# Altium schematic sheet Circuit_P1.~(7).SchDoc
size 431 x 279 mm; Date: Not shown in title block; ApprovedBy: Not shown in title block; CheckedBy: Not shown in title block; Author: Not shown in title block; CompanyName: Not shown in title block; Engineer: Not shown in title block; Organization: Not shown in title block; Address1: Not shown in title block; Address2: Not shown in title block; Address3: Not shown in title block; Address4: Not shown in title block; DocumentNumber: 1; Revision: Use project parameter SCH_Rev; SheetNumber: 1; SheetTotal: 2; PageSetup: Record=PageOptions¦CenterHorizontal=True¦CenterVertical=True¦PrintScale=1.00¦XCorrection=1.00¦YCorrection=1.00¦PrintKind=0¦BorderSize=5000000¦LeftOffset=0¦BottomOffset=0¦Orientation=2¦PaperLength=1000¦PaperWidth=1000¦Scale=100¦PaperSource=15¦PrintQuality=600¦MediaType=1¦DitherType=10¦PaperKind=Letter¦PrintScaleMode=1
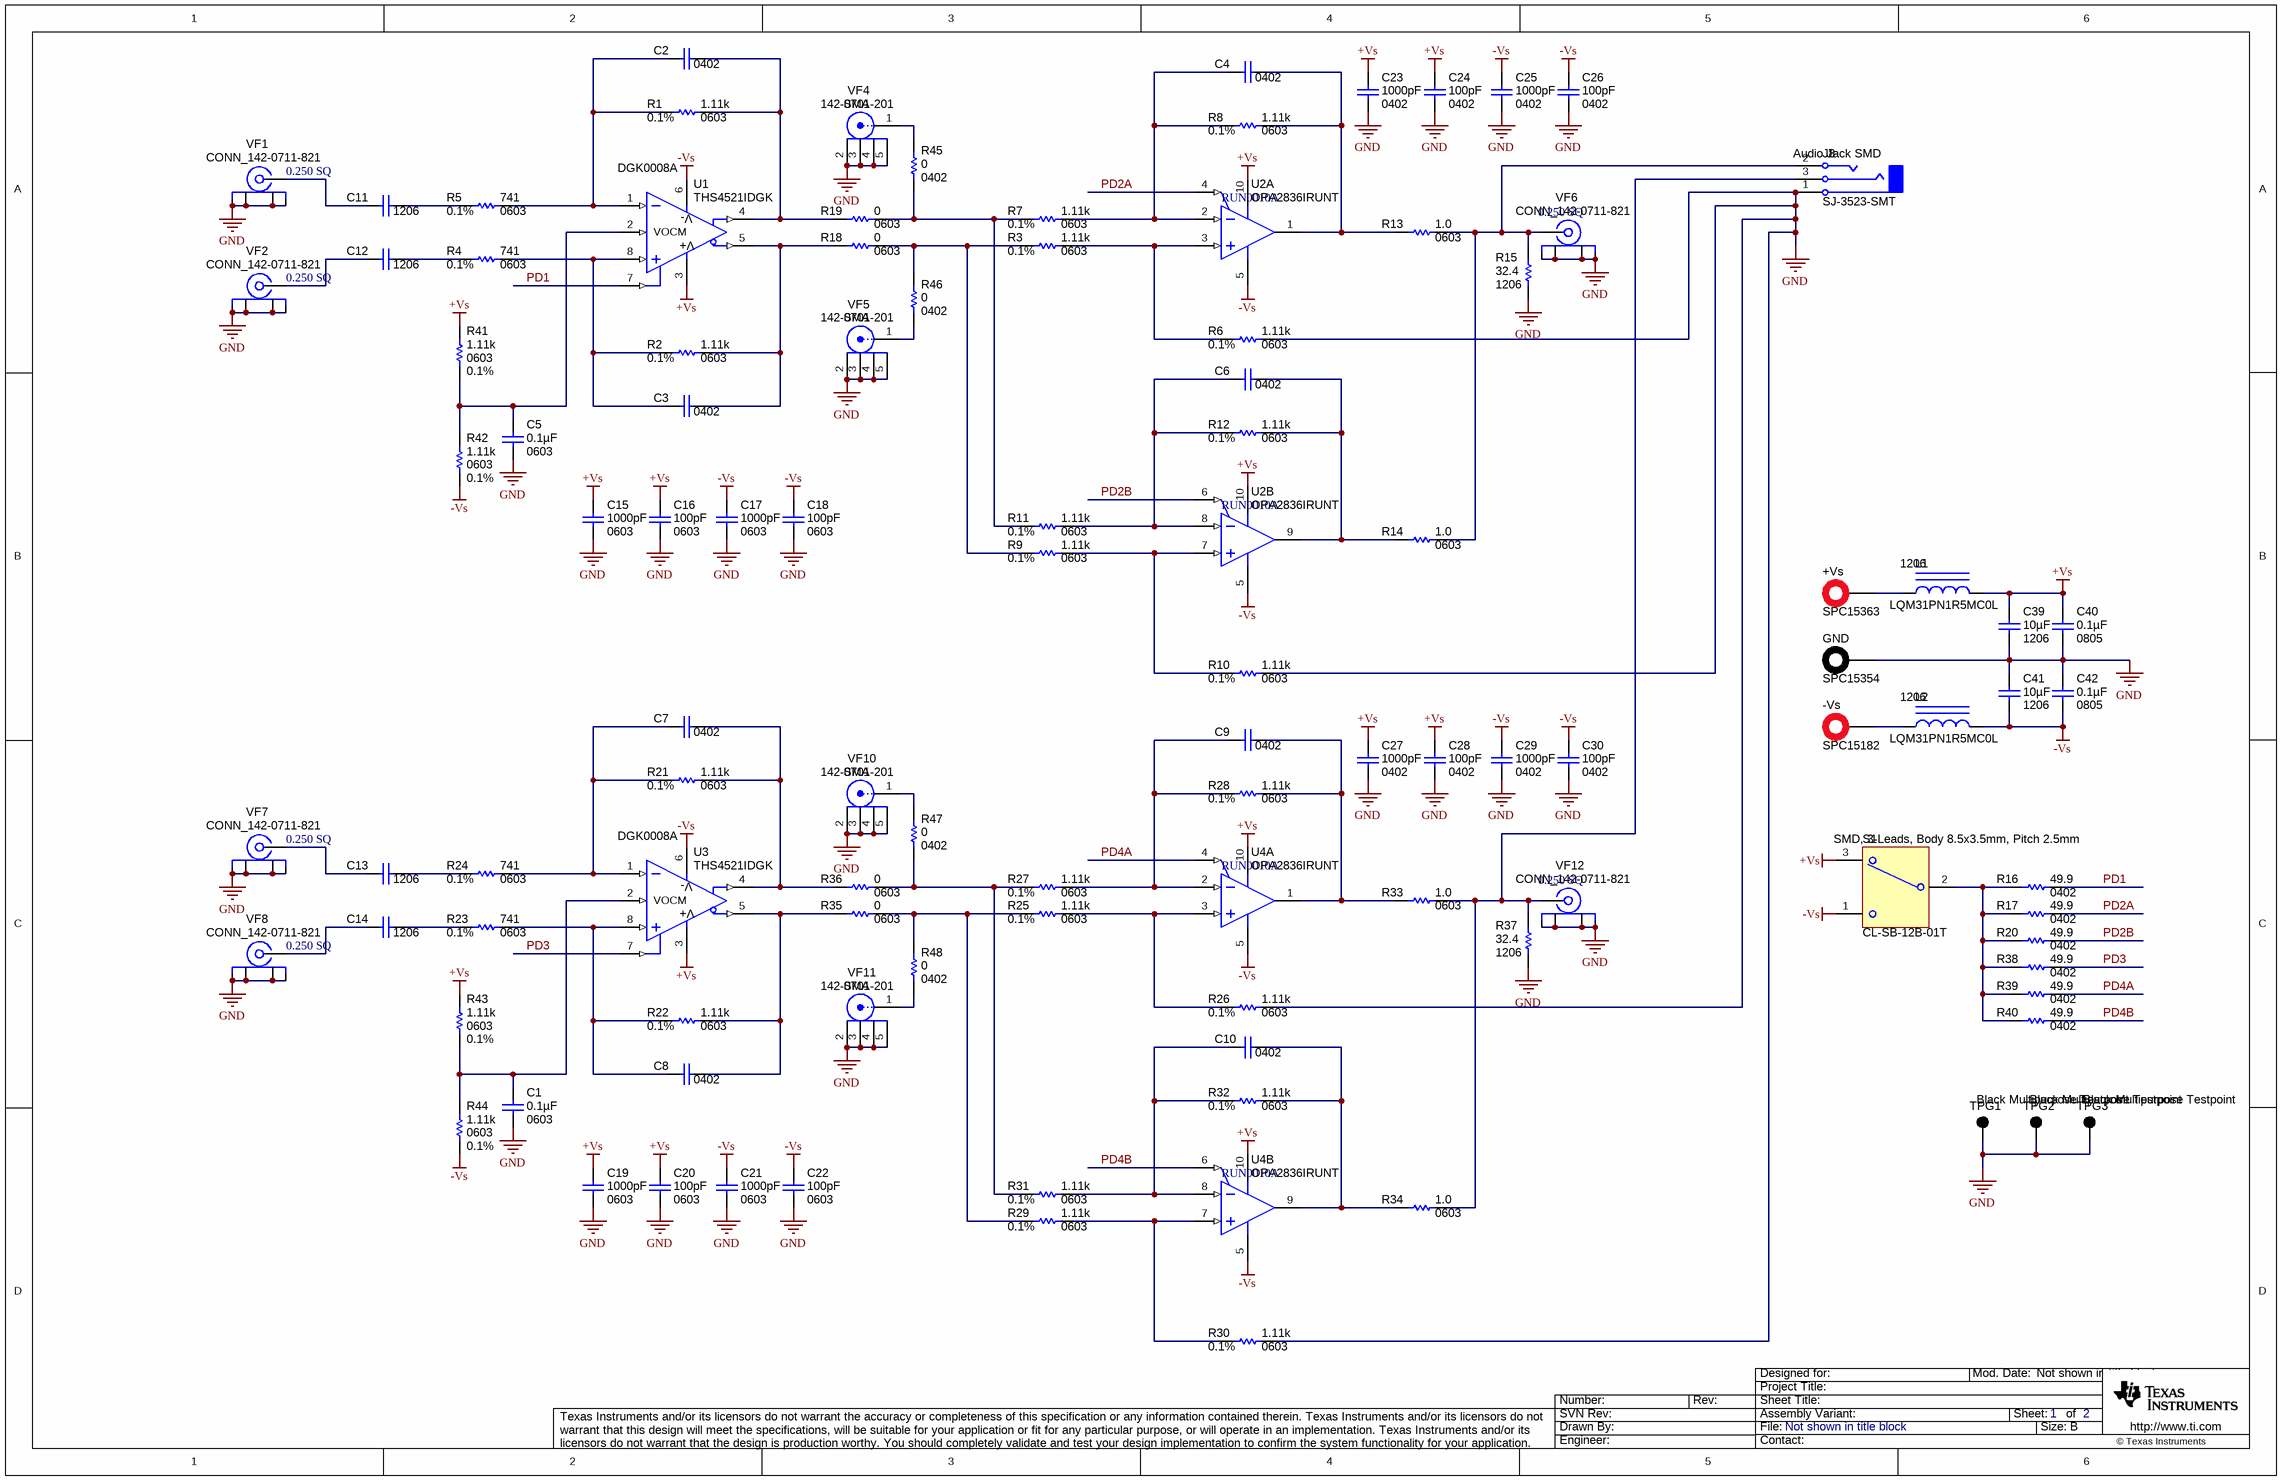
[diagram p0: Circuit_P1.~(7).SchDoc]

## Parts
+Vs  SPC15363  [Tenma_SPC15363]
-Vs  SPC15182  [Tenma_SPC15363]
C1  ValueDisplayed: 0.1µF  PackageReference: 0603  [0603L]  (hidden comment: C1608X7R1H104K)
C2  PackageReference: 0402  [0402L]
C3  PackageReference: 0402  [0402L]
C4  PackageReference: 0402  [0402L]
C5  ValueDisplayed: 0.1µF  PackageReference: 0603  [0603L]  (hidden comment: C1608X7R1H104K)
C6  PackageReference: 0402  [0402L]
C7  PackageReference: 0402  [0402L]
C8  PackageReference: 0402  [0402L]
C9  PackageReference: 0402  [0402L]
C10  PackageReference: 0402  [0402L]
C11  PackageReference: 1206  [1206L]
C12  PackageReference: 1206  [1206L]
C13  PackageReference: 1206  [1206L]
C14  PackageReference: 1206  [1206L]
C15  ValueDisplayed: 1000pF  PackageReference: 0603  [0603L]  (hidden comment: C1608C0G1H102J)
C16  ValueDisplayed: 100pF  PackageReference: 0603  [0603L]  (hidden comment: 06035A101JAT2A)
C17  ValueDisplayed: 1000pF  PackageReference: 0603  [0603L]  (hidden comment: C1608C0G1H102J)
C18  ValueDisplayed: 100pF  PackageReference: 0603  [0603L]  (hidden comment: 06035A101JAT2A)
C19  ValueDisplayed: 1000pF  PackageReference: 0603  [0603L]  (hidden comment: C1608C0G1H102J)
C20  ValueDisplayed: 100pF  PackageReference: 0603  [0603L]  (hidden comment: 06035A101JAT2A)
C21  ValueDisplayed: 1000pF  PackageReference: 0603  [0603L]  (hidden comment: C1608C0G1H102J)
C22  ValueDisplayed: 100pF  PackageReference: 0603  [0603L]  (hidden comment: 06035A101JAT2A)
C23  ValueDisplayed: 1000pF  PackageReference: 0402  [0402L]  (hidden comment: C1005C0G1E102J)
C24  ValueDisplayed: 100pF  PackageReference: 0402  [0402L]  (hidden comment: CC0402JRNPO9BN101)
C25  ValueDisplayed: 1000pF  PackageReference: 0402  [0402L]  (hidden comment: C1005C0G1E102J)
C26  ValueDisplayed: 100pF  PackageReference: 0402  [0402L]  (hidden comment: CC0402JRNPO9BN101)
C27  ValueDisplayed: 1000pF  PackageReference: 0402  [0402L]  (hidden comment: C1005C0G1E102J)
C28  ValueDisplayed: 100pF  PackageReference: 0402  [0402L]  (hidden comment: CC0402JRNPO9BN101)
C29  ValueDisplayed: 1000pF  PackageReference: 0402  [0402L]  (hidden comment: C1005C0G1E102J)
C30  ValueDisplayed: 100pF  PackageReference: 0402  [0402L]  (hidden comment: CC0402JRNPO9BN101)
C39  ValueDisplayed: 10µF  PackageReference: 1206  [1206L]  (hidden comment: GRM31CR61E106KA12L)
C40  ValueDisplayed: 0.1µF  PackageReference: 0805  [0805L]  (hidden comment: 08055C104KAT2A)
C41  ValueDisplayed: 10µF  PackageReference: 1206  [1206L]  (hidden comment: GRM31CR61E106KA12L)
C42  ValueDisplayed: 0.1µF  PackageReference: 0805  [0805L]  (hidden comment: 08055C104KAT2A)
GND  SPC15354  [Tenma_SPC15354]
J8  SJ-3523-SMT  PackageReference: Audio Jack SMD  [CUI_SJ-3523-SMT]
L1  LQM31PN1R5MC0L  PackageReference: 1206  [1206L]
L2  LQM31PN1R5MC0L  PackageReference: 1206  [1206L]
R1  ValueDisplayed: 1.11k  PackageReference: 0603  Value1: 0.1%  [0603L]  (hidden comment: RT0603BRD071K11L)
R2  ValueDisplayed: 1.11k  PackageReference: 0603  Value1: 0.1%  [0603L]  (hidden comment: RT0603BRD071K11L)
R3  ValueDisplayed: 1.11k  PackageReference: 0603  Value1: 0.1%  [0603L]  (hidden comment: RT0603BRD071K11L)
R4  ValueDisplayed: 741  PackageReference: 0603  Value1: 0.1%  [0603L]  (hidden comment: RT0603BRD07741RL)
R5  ValueDisplayed: 741  PackageReference: 0603  Value1: 0.1%  [0603L]  (hidden comment: RT0603BRD07741RL)
R6  ValueDisplayed: 1.11k  PackageReference: 0603  Value1: 0.1%  [0603L]  (hidden comment: RT0603BRD071K11L)
R7  ValueDisplayed: 1.11k  PackageReference: 0603  Value1: 0.1%  [0603L]  (hidden comment: RT0603BRD071K11L)
R8  ValueDisplayed: 1.11k  PackageReference: 0603  Value1: 0.1%  [0603L]  (hidden comment: RT0603BRD071K11L)
R9  ValueDisplayed: 1.11k  PackageReference: 0603  Value1: 0.1%  [0603L]  (hidden comment: RT0603BRD071K11L)
R10  ValueDisplayed: 1.11k  PackageReference: 0603  Value1: 0.1%  [0603L]  (hidden comment: RT0603BRD071K11L)
R11  ValueDisplayed: 1.11k  PackageReference: 0603  Value1: 0.1%  [0603L]  (hidden comment: RT0603BRD071K11L)
R12  ValueDisplayed: 1.11k  PackageReference: 0603  Value1: 0.1%  [0603L]  (hidden comment: RT0603BRD071K11L)
R13  ValueDisplayed: 1.0  PackageReference: 0603  [0603L]  (hidden comment: CRCW06031R00JNEA)
R14  ValueDisplayed: 1.0  PackageReference: 0603  [0603L]  (hidden comment: CRCW06031R00JNEA)
R15  ValueDisplayed: 32.4  PackageReference: 1206  [1206L]  (hidden comment: CRCW120632R4FKEA)
R16  ValueDisplayed: 49.9  PackageReference: 0402  [0402L]  (hidden comment: CRCW040249R9FKED)
R17  ValueDisplayed: 49.9  PackageReference: 0402  [0402L]  (hidden comment: CRCW040249R9FKED)
R18  ValueDisplayed: 0  PackageReference: 0603  [0603L]  (hidden comment: CRCW06030000Z0EA)
R19  ValueDisplayed: 0  PackageReference: 0603  [0603L]  (hidden comment: CRCW06030000Z0EA)
R20  ValueDisplayed: 49.9  PackageReference: 0402  [0402L]  (hidden comment: CRCW040249R9FKED)
R21  ValueDisplayed: 1.11k  PackageReference: 0603  Value1: 0.1%  [0603L]  (hidden comment: RT0603BRD071K11L)
R22  ValueDisplayed: 1.11k  PackageReference: 0603  Value1: 0.1%  [0603L]  (hidden comment: RT0603BRD071K11L)
R23  ValueDisplayed: 741  PackageReference: 0603  Value1: 0.1%  [0603L]  (hidden comment: RT0603BRD07741RL)
R24  ValueDisplayed: 741  PackageReference: 0603  Value1: 0.1%  [0603L]  (hidden comment: RT0603BRD07741RL)
R25  ValueDisplayed: 1.11k  PackageReference: 0603  Value1: 0.1%  [0603L]  (hidden comment: RT0603BRD071K11L)
R26  ValueDisplayed: 1.11k  PackageReference: 0603  Value1: 0.1%  [0603L]  (hidden comment: RT0603BRD071K11L)
R27  ValueDisplayed: 1.11k  PackageReference: 0603  Value1: 0.1%  [0603L]  (hidden comment: RT0603BRD071K11L)
R28  ValueDisplayed: 1.11k  PackageReference: 0603  Value1: 0.1%  [0603L]  (hidden comment: RT0603BRD071K11L)
R29  ValueDisplayed: 1.11k  PackageReference: 0603  Value1: 0.1%  [0603L]  (hidden comment: RT0603BRD071K11L)
R30  ValueDisplayed: 1.11k  PackageReference: 0603  Value1: 0.1%  [0603L]  (hidden comment: RT0603BRD071K11L)
R31  ValueDisplayed: 1.11k  PackageReference: 0603  Value1: 0.1%  [0603L]  (hidden comment: RT0603BRD071K11L)
R32  ValueDisplayed: 1.11k  PackageReference: 0603  Value1: 0.1%  [0603L]  (hidden comment: RT0603BRD071K11L)
R33  ValueDisplayed: 1.0  PackageReference: 0603  [0603L]  (hidden comment: CRCW06031R00JNEA)
R34  ValueDisplayed: 1.0  PackageReference: 0603  [0603L]  (hidden comment: CRCW06031R00JNEA)
R35  ValueDisplayed: 0  PackageReference: 0603  [0603L]  (hidden comment: CRCW06030000Z0EA)
R36  ValueDisplayed: 0  PackageReference: 0603  [0603L]  (hidden comment: CRCW06030000Z0EA)
R37  ValueDisplayed: 32.4  PackageReference: 1206  [1206L]  (hidden comment: CRCW120632R4FKEA)
R38  ValueDisplayed: 49.9  PackageReference: 0402  [0402L]  (hidden comment: CRCW040249R9FKED)
R39  ValueDisplayed: 49.9  PackageReference: 0402  [0402L]  (hidden comment: CRCW040249R9FKED)
R40  ValueDisplayed: 49.9  PackageReference: 0402  [0402L]  (hidden comment: CRCW040249R9FKED)
R41  ValueDisplayed: 1.11k  PackageReference: 0603  Value1: 0.1%  [0603L]  (hidden comment: RT0603BRD071K11L)
R42  ValueDisplayed: 1.11k  PackageReference: 0603  Value1: 0.1%  [0603L]  (hidden comment: RT0603BRD071K11L)
R43  ValueDisplayed: 1.11k  PackageReference: 0603  Value1: 0.1%  [0603L]  (hidden comment: RT0603BRD071K11L)
R44  ValueDisplayed: 1.11k  PackageReference: 0603  Value1: 0.1%  [0603L]  (hidden comment: RT0603BRD071K11L)
R45  ValueDisplayed: 0  PackageReference: 0402  [0402L]  (hidden comment: CRCW04020000Z0ED)
R46  ValueDisplayed: 0  PackageReference: 0402  [0402L]  (hidden comment: CRCW04020000Z0ED)
R47  ValueDisplayed: 0  PackageReference: 0402  [0402L]  (hidden comment: CRCW04020000Z0ED)
R48  ValueDisplayed: 0  PackageReference: 0402  [0402L]  (hidden comment: CRCW04020000Z0ED)
S1  CL-SB-12B-01T  PackageReference: SMD, 3-Leads, Body 8.5x3.5mm, Pitch 2.5mm  [SW_CL-SB-12B-01]
TPG1  PackageReference: Black Multipurpose Testpoint  [Keystone5011]  (hidden comment: 5011)
TPG2  PackageReference: Black Multipurpose Testpoint  [Keystone5011]  (hidden comment: 5011)
TPG3  PackageReference: Black Multipurpose Testpoint  [Keystone5011]  (hidden comment: 5011)
U1  THS4521IDGK  PackageReference: DGK0008A  [DGK0008A_N]
U2  OPA2836IRUNT  [RUN0010A]  (parts A,B of 2)
U3  THS4521IDGK  PackageReference: DGK0008A  [DGK0008A_N]
U4  OPA2836IRUNT  [RUN0010A]  (parts A,B of 2)
VF1  CONN_142-0711-821  PackageReference: 0.250 SQ  [CONN_142-0711-821]
VF2  CONN_142-0711-821  PackageReference: 0.250 SQ  [CONN_142-0711-821]
VF4  142-0701-201  PackageReference: SMA  [Johnson_142-0701-20x]
VF5  142-0701-201  PackageReference: SMA  [Johnson_142-0701-20x]
VF6  CONN_142-0711-821  PackageReference: 0.250 SQ  [CONN_142-0711-821]
VF7  CONN_142-0711-821  PackageReference: 0.250 SQ  [CONN_142-0711-821]
VF8  CONN_142-0711-821  PackageReference: 0.250 SQ  [CONN_142-0711-821]
VF10  142-0701-201  PackageReference: SMA  [Johnson_142-0701-20x]
VF11  142-0701-201  PackageReference: SMA  [Johnson_142-0701-20x]
VF12  CONN_142-0711-821  PackageReference: 0.250 SQ  [CONN_142-0711-821]

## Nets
+Vs: C15.1 C16.1 C19.1 C20.1 C23.1 C24.1 C27.1 C28.1 C39.1 C40.1 L1.2 R41.2 R43.2 S1.3 U1.3(VS+) U2.10(VS+) U3.3(VS+) U4.10(VS+)
-Vs: C17.1 C18.1 C21.1 C22.1 C25.1 C26.1 C29.1 C30.1 C41.2 C42.2 L2.2 R42.1 R44.1 S1.1 U1.6(VS-) U2.5(VS-) U3.6(VS-) U4.5(VS-)
GND: C1.2 C5.2 C15.2 C16.2 C17.2 C18.2 C19.2 C20.2 C21.2 C22.2 C23.2 C24.2 C25.2 C26.2 C27.2 C28.2 C29.2 C30.2 C39.2 C40.2 C41.1 C42.1 GND.1 J8.1(SLEEVE) R6.2 R10.2 R15.1 R26.2 R30.2 R37.1 TPG1.1 TPG2.1 TPG3.1 VF1.2(GND) VF1.3(GND) VF1.4 VF1.5(GND) VF2.2(GND) VF2.3(GND) VF2.4 VF2.5(GND) VF4.2 VF4.3 VF4.4 VF4.5 VF5.2 VF5.3 VF5.4 VF5.5 VF6.2(GND) VF6.3(GND) VF6.4 VF6.5(GND) VF7.2(GND) VF7.3(GND) VF7.4 VF7.5(GND) VF8.2(GND) VF8.3(GND) VF8.4 VF8.5(GND) VF10.2 VF10.3 VF10.4 VF10.5 VF11.2 VF11.3 VF11.4 VF11.5 VF12.2(GND) VF12.3(GND) VF12.4 VF12.5(GND)
PD1: R16.2 U1.7(~{PD})
PD2A: R17.2 U2.4(~{PD1})
PD2B: R20.2 U2.6(~{PD2})
PD3: R38.2 U3.7(~{PD})
PD4A: R39.2 U4.4(~{PD1})
PD4B: R40.2 U4.6(~{PD2})
Net+Vs_1: +Vs.1 L1.1
Net-Vs_1: -Vs.1 L2.1
NetC1_1: C1.1 R43.1 R44.2 U3.2(VOCM)
NetC2_1: C2.1 R1.2 R19.1 U1.4(VOUT+)
NetC2_2: C2.2 R1.1 R5.2 U1.1(VIN-)
NetC3_1: C3.1 R2.2 R18.1 U1.5(VOUT-)
NetC3_2: C3.2 R2.1 R4.2 U1.8(VIN+)
NetC4_1: C4.1 R8.2 R13.1 U2.1(VOUT1)
NetC4_2: C4.2 R7.2 R8.1 U2.2(VIN1-)
NetC5_1: C5.1 R41.1 R42.2 U1.2(VOCM)
NetC6_1: C6.1 R12.2 R14.1 U2.9(VOUT2)
NetC6_2: C6.2 R11.2 R12.1 U2.8(VIN2-)
NetC7_1: C7.1 R21.2 R36.1 U3.4(VOUT+)
NetC7_2: C7.2 R21.1 R24.2 U3.1(VIN-)
NetC8_1: C8.1 R22.2 R35.1 U3.5(VOUT-)
NetC8_2: C8.2 R22.1 R23.2 U3.8(VIN+)
NetC9_1: C9.1 R28.2 R33.1 U4.1(VOUT1)
NetC9_2: C9.2 R27.2 R28.1 U4.2(VIN1-)
NetC10_1: C10.1 R32.2 R34.1 U4.9(VOUT2)
NetC10_2: C10.2 R31.2 R32.1 U4.8(VIN2-)
NetC11_1: C11.1 R5.1
NetC11_2: C11.2 VF1.1(SIGNAL)
NetC12_1: C12.1 R4.1
NetC12_2: C12.2 VF2.1(SIGNAL)
NetC13_1: C13.1 R24.1
NetC13_2: C13.2 VF7.1(SIGNAL)
NetC14_1: C14.1 R23.1
NetC14_2: C14.2 VF8.1(SIGNAL)
NetJ8_2: J8.2(TIP) R13.2 R14.2 R15.2 VF6.1(SIGNAL)
NetJ8_3: J8.3(RING) R33.2 R34.2 R37.2 VF12.1(SIGNAL)
NetR3_1: R3.1 R9.1 R18.2 R46.2
NetR3_2: R3.2 R6.1 U2.3(VIN1+)
NetR7_1: R7.1 R11.1 R19.2 R45.1
NetR9_2: R9.2 R10.1 U2.7(VIN2+)
NetR16_1: R16.1 R17.1 R20.1 R38.1 R39.1 R40.1 S1.2(COM)
NetR25_1: R25.1 R29.1 R35.2 R48.2
NetR25_2: R25.2 R26.1 U4.3(VIN1+)
NetR27_1: R27.1 R31.1 R36.2 R47.1
NetR29_2: R29.2 R30.1 U4.7(VIN2+)
NetR45_2: R45.2 VF4.1
NetR46_1: R46.1 VF5.1
NetR47_2: R47.2 VF10.1
NetR48_1: R48.1 VF11.1

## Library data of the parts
+Vs = SPC15363: BANANA JACK, SOLDER LUG, RED, TH; Manufacturer: Tenma; SymbolCreator: a0412235; U/M: EA
-Vs = SPC15363: BANANA JACK, SOLDER LUG, GREEN, TH; Manufacturer: Tenma; SymbolCreator: a0412235; U/M: EA
C1 C5 = C1608X7R1H104K: CAP, CERM, 0.1 µF, 50 V, +/- 10%, X7R, 0603; Manufacturer: TDK; Polarized: N; CompType: Capacitor; Value: 0.1uF; U/M: EA; Cap_F: 0.0000001; Tolerance_%: 10; ESR_ohm: 0.017; Value1: 0.017 ohm; VDC_V: 50; Value2: 50V; TaMin_C: -55; TaMax_C: 125
C2-C4 C6-C14 = Capacitor: CAP, CERM, xxxF, xxV, [TempCo], xx%, [PackageReference]; Manufacturer: Used in BOM report; Polarized: N; U/M: EA
C15 C17 C19 C21 = C1608C0G1H102J: CAP, CERM, 1000 pF, 50 V, +/- 5%, C0G/NP0, 0603; Manufacturer: TDK; Polarized: N; CompType: Capacitor; Value: 1000pF; U/M: EA; Cap_F: 0.000000001; Tolerance_%: 5; ESR_ohm: 0.0563; Value1: 0.0563 ohm; VDC_V: 50; Value2: 50V; TaMin_C: -55; TaMax_C: 125
C16 C18 C20 C22 = 06035A101JAT2A: CAP, CERM, 100 pF, 50 V, +/- 5%, C0G/NP0, 0603; Manufacturer: AVX; Polarized: N; CompType: Capacitor; Value: 100pF; U/M: EA; Cap_F: 0.0000000001; Tolerance_%: 5; ESR_ohm: 0.119; Value1: 0.119 ohm; VDC_V: 50; Value2: 50V; TaMin_C: -55; TaMax_C: 125
C23 C25 C27 C29 = C1005C0G1E102J: CAP, CERM, 1000 pF, 25 V, +/- 5%, C0G/NP0, 0402; Manufacturer: TDK; Polarized: N; CompType: Capacitor; Value: 1000pF; U/M: EA; Cap_F: 0.000000001; Tolerance_%: 5; Value1: Unknown; VDC_V: 25; Value2: 25V; TaMin_C: -55; TaMax_C: 125
C24 C26 C28 C30 = CC0402JRNPO9BN101: CAP, CERM, 100 pF, 50 V, +/- 5%, C0G/NP0, 0402; Manufacturer: Yageo America; Polarized: N; CompType: Capacitor; Value: 100pF; U/M: EA; Cap_F: 0.0000000001; Tolerance_%: 5; Value1: Unknown; VDC_V: 50; Value2: 50V; TaMin_C: -55; TaMax_C: 125
C39 C41 = GRM31CR61E106KA12L: CAP, CERM, 10 µF, 25 V, +/- 10%, X5R, 1206; Manufacturer: MuRata; Polarized: N; CompType: Capacitor; Value: 10uF; U/M: EA; Cap_F: 0.00001; Tolerance_%: 10; ESR_ohm: 0.004; Value1: 0.004 ohm; VDC_V: 25; Value2: 25V; TaMin_C: -55; TaMax_C: 85
C40 C42 = 08055C104KAT2A: CAP, CERM, 0.1 µF, 50 V, +/- 10%, X7R, 0805; Manufacturer: AVX; Polarized: N; CompType: Capacitor; Value: 0.1uF; U/M: EA; Cap_F: 0.0000001; Tolerance_%: 10; ESR_ohm: 0.024; Value1: 0.024 ohm; VDC_V: 50; Value2: 50V; TaMin_C: -55; TaMax_C: 125
GND = SPC15354: BANANA JACK, SOLDER LUG, BLACK, TH; Manufacturer: Tenma; SymbolCreator: a0412235; U/M: EA
J8 = SJ-3523-SMT: Audio Jack, 3.5mm, Stereo, R/A, SMT; Manufacturer: CUI Inc.; SymbolCreator: a0412235; U/M: EA
L1 L2 = LQM31PN1R5MC0L: Inductor, Multilayer, Ferrite, 1.5 µH, 1 A, 0.17 ohm, SMD; Manufacturer: MuRata; Value: 1.5uH; Ind_H: 1.5E-6; ValueDisplayed: 1.5µH; Imax_A: 1; Irms: 1A @ 40C rise; DCR_ohm: 0.17; Value2: 1A
R1-R3 R6-R12 R21 R22 R25-R32 R41-R44 = RT0603BRD071K11L: RES, 1.11 k, 0.1%, 0.1 W, 0603; Manufacturer: Yageo America; CompType: Resistor; Value: 1.11k; Res_ohm: 1110; Value_Code: 1k11; Tolerance_%: 0.1; Value2: 0.1W; VDC_V: 75; TempCo: 25 ppm/C; EIA_Code: E192; U/M: EA
R4 R5 R23 R24 = RT0603BRD07741RL: RES, 741, 0.1%, 0.1 W, 0603; Manufacturer: Yageo America; CompType: Resistor; Value: 741; Value_Code: 741R; Tolerance_%: 0.1; Value2: 0.1W; VDC_V: 75; TempCo: 25 ppm/C; EIA_Code: E192; U/M: EA
R13 R14 R33 R34 = CRCW06031R00JNEA: RES, 1.0, 5%, 0.1 W, 0603; Manufacturer: Vishay-Dale; CompType: Resistor; Value: 1.0; Res_ohm: 1; Value_Code: 1R00; Tolerance_%: 5; Power_W: 0.1; Value2: 0.1W; VDC_V: 75; TempCo: 200 ppm/C; EIA_Code: E24; U/M: EA
R15 R37 = CRCW120632R4FKEA: RES, 32.4, 1%, 0.25 W, 1206; Manufacturer: Vishay-Dale; CompType: Resistor; Value: 32.4; Value_Code: 32R4; Tolerance_%: 1; Power_W: 0.25; Value2: 0.25W; VDC_V: 200; TempCo: 100 ppm/C; EIA_Code: E96; U/M: EA
R16 R17 R20 R38-R40 = CRCW040249R9FKED: RES, 49.9, 1%, 0.063 W, 0402; Manufacturer: Vishay-Dale; CompType: Resistor; Value: 49.9; Value_Code: 49R9; Tolerance_%: 1; Power_W: 0.063; Value2: 0.063W; VDC_V: 50; TempCo: 100 ppm/C; EIA_Code: E96; U/M: EA
R18 R19 R35 R36 = CRCW06030000Z0EA: RES, 0, 5%, 0.1 W, 0603; Manufacturer: Vishay-Dale; CompType: Resistor; Value: 0; Value_Code: 0000; Tolerance_%: 5; Power_W: 0.1; Value2: 0.1W; VDC_V: 75; TempCo: 200 ppm/C; EIA_Code: E24; U/M: EA
R45-R48 = CRCW04020000Z0ED: RES, 0, 5%, 0.063 W, 0402; Manufacturer: Vishay-Dale; CompType: Resistor; Value: 0; Value_Code: 0000; Tolerance_%: 5; Power_W: 0.063; Value2: 0.063W; VDC_V: 50; TempCo: 200 ppm/C; EIA_Code: E24; U/M: EA
S1 = CL-SB-12B-01T: Switch, Slide, SPDT, 0.2A, GULL, 12V, SMD; Manufacturer: Copal Electronics; SymbolCreator: x0208326; VDC_V: 12; SwitchFunction: On-On; PositionCount: 2; CurrentRating_mA: 200
TPG1-TPG3 = 5011: Test Point, Multipurpose, Black, TH; Manufacturer: Keystone; CompType: Test Point Loop; U/M: EA
U1 U3 = THS4521IDGK: VERY LOW POWER, NEGATIVE RAIL INPUT, RAIL-TO-RAIL OUTPUT, FULLY DIFFERENTIAL AMPLIFIER, DGK0008A; Manufacturer: Texas Instruments; SymbolCreator: a0411947; CompType: IC; U/M: EA
U2 U4 = OPA2836IRUNT: Dual, Very Low Power, Rail to Rail Out, Negative Rail In, VFB Operational Amplifier, 2.5 to 5.5 V, -40 to 85 degC, 10-pin QFN (RUN0010A), Green (RoHS & no Sb/Br); Manufacturer: Texas Instruments; Alternate Manufacturer: None; Alternate PartNumber: Equivalent; 2nd Harmonic(dBc): 85; 3rd Harmonic(dBc): 105; Acl, min stable gain(V/V): 1; BW @ Acl(MHz): 205; Iib(Max)(nA): 1550; Io(Typ)(mA): 50; Iq per channel(Max)(mA): 1.2; Number of Channels: 2; Settling Time (0.1%)(Typ)(ns): 30; Slew Rate(Typ)(V/us): 560; Sub Family: High Output Current Amplifier (>=50mA), High Speed Amplifier (>=50MHz), Low Noise Amp (<=10nV/rtHz), Low Offset Voltage Amplifier (<=500uV), Low Supply Voltage Amplifier (<=2.7V); THD (Fc is 1 MHz)(Typ)(dB): -130; Vio(Max)(mV): 0.4; Vn at Flatband(Typ)(nV/rtHz): 4.6; Vs(Max)(V): 5.5; Vs(Min)(V): 2.5
VF1 VF2 VF6-VF8 VF12 = CONN_142-0711-821: CONNECTOR, SHEILDED, END LAUNCH JACK, GOLD PLATED, FOR 0.062 PCB, EDGE MOUNTED; Manufacturer: Cinch Connectivity Solutions Johnson; area: 95000
VF4 VF5 VF10 VF11 = 142-0701-201: Connector, TH, SMA; Manufacturer: Emerson Network Power; SymbolCreator: X0208326; U/M: EA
